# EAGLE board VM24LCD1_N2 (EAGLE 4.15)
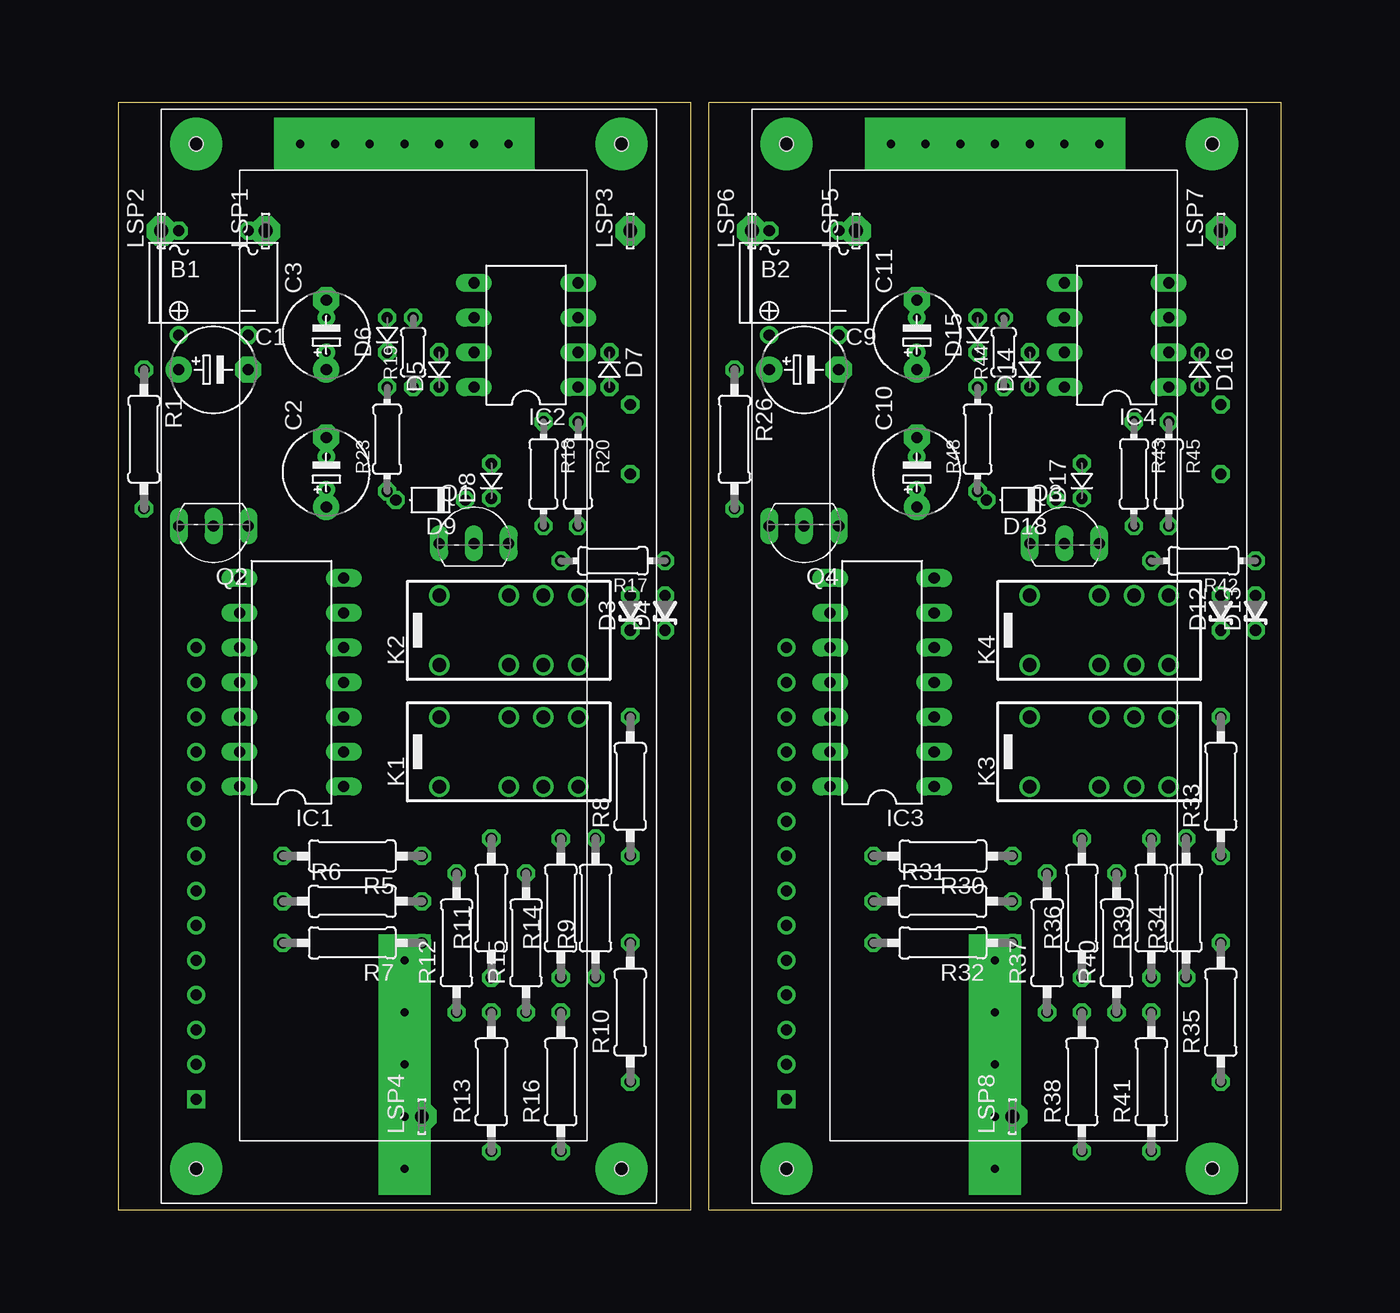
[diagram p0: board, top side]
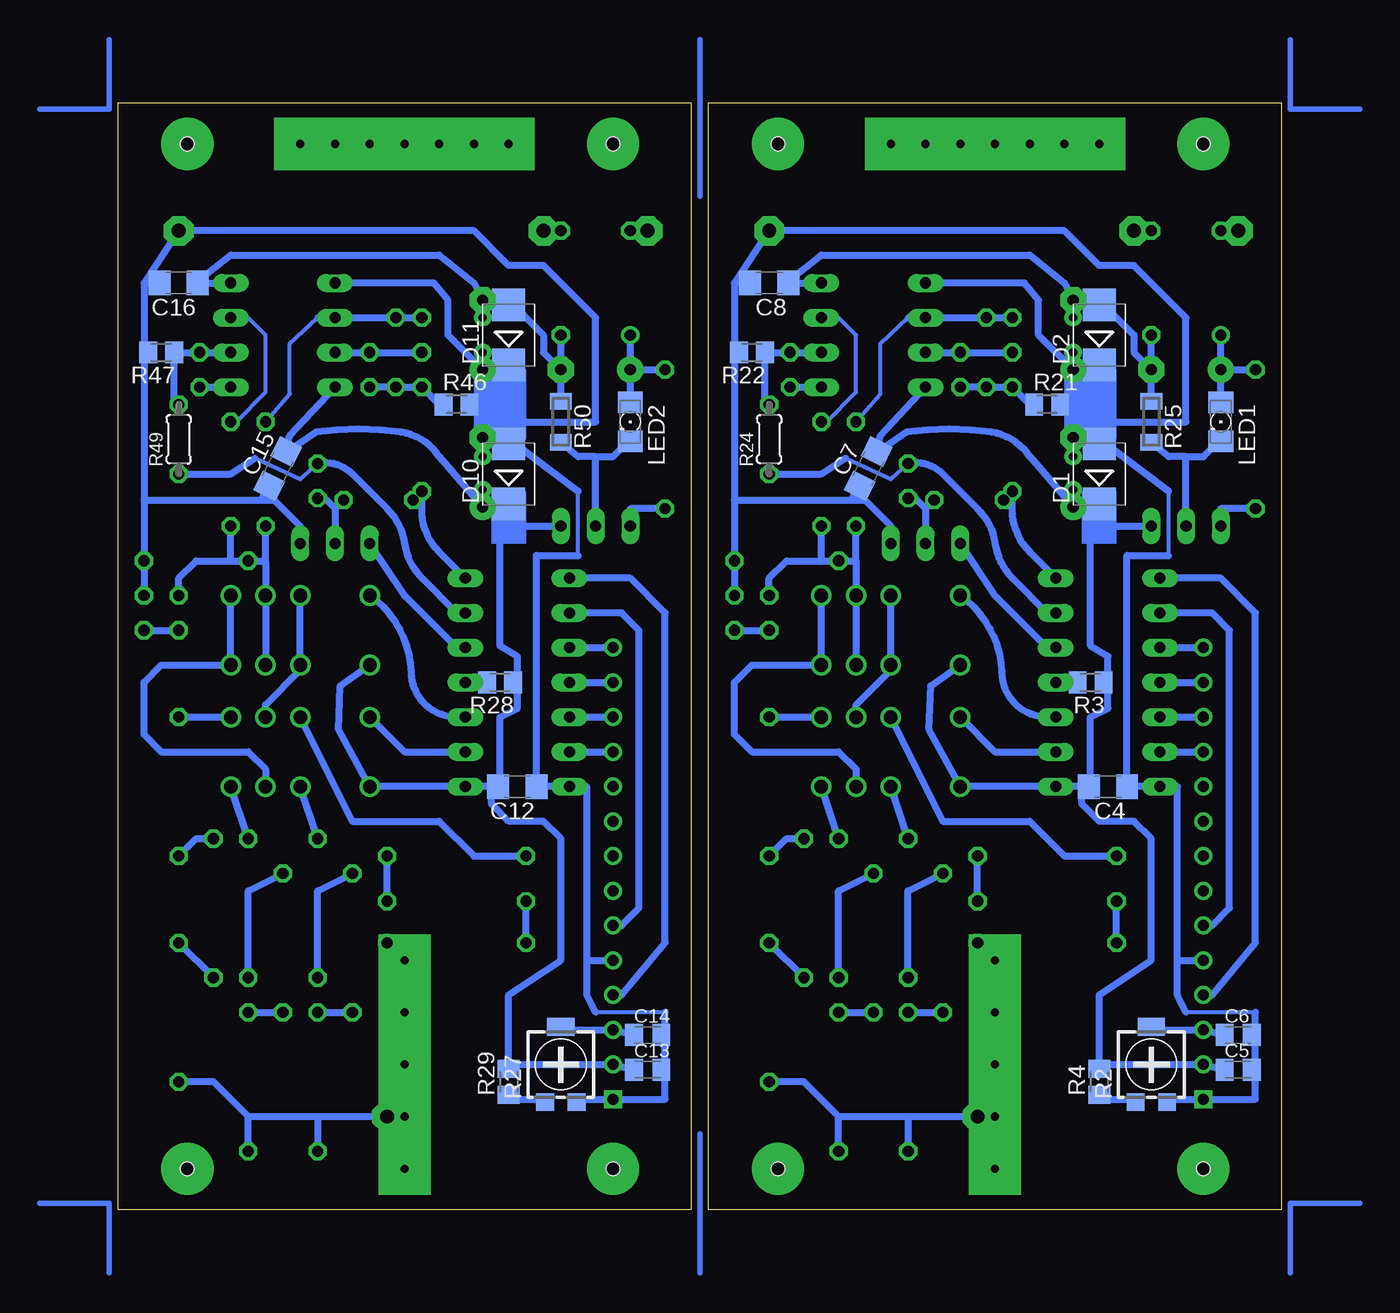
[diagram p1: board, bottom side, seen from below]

Size 85.08 x 80.95 mm. Coordinates in mm from the lower left corner, seen from the top.
Outline: 41.9,0 41.9,80.95 0,80.95 0,0 41.9,0
Outline: 85.08,0 85.08,80.95 43.18,80.95 43.18,0 85.08,0
Copper layers (1*16): Top 0.035mm / dielectric 1.5mm / Bottom 0.035mm
Design rules "default": minimum track width 10mil, minimum drill 24mil, track to track 8mil, track to pad 8mil, pad to pad 8mil, via to via 8mil, smd to smd 8mil, copper to edge 40mil, drill to drill 8mil, minimum pad ring 10mil, minimum via ring 8mil, stop-mask expansion 4mil, vias tented up to drill 0mil, thermal gap 10mil

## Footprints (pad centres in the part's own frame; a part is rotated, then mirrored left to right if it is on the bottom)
B-DIL = drill 0.813 round: + -2.54,-3.81 | drill 0.813 octagon: - 2.54,-3.81; AC1 2.54,3.81; AC2 -2.54,3.81
E5-6 = drill 0.813 pad 1.905 round: + -2.54,0 | drill 0.813 pad 1.905 octagon: - 2.54,0
C1206 = smd 1.6 x 1.8: 1 -1.4,0; 2 1.4,0
C0805K = smd 1.3 x 1.6: 1 -1,0; 2 1,0
SMB = smd 2.4 x 2.4: A 2.2,0; C -2.2,0
ZDIO-2.5 = drill 0.813 octagon: A 1.27,0; C -1.27,0
D-2.5 = drill 0.813 octagon: A 1.27,0; C -1.27,0
D-5 = drill 0.813 octagon: A 2.54,0; C -2.54,0
DIL14 = drill 0.813 long: 1 -7.62,-3.81; 2 -5.08,-3.81; 3 -2.54,-3.81; 4 0,-3.81; 5 2.54,-3.81; 6 5.08,-3.81; 7 7.62,-3.81; 8 7.62,3.81; 9 5.08,3.81; 10 2.54,3.81; 11 0,3.81; 12 -2.54,3.81; 13 -5.08,3.81; 14 -7.62,3.81
DIL08 = drill 0.813 long: 1 -3.81,-3.81; 2 -1.27,-3.81; 3 1.27,-3.81; 4 3.81,-3.81; 5 3.81,3.81; 6 1.27,3.81; 7 -1.27,3.81; 8 -3.81,3.81
TX2 = drill 1 round: 1 -5.08,-2.54; 3 0,-2.54; 4 2.54,-2.54; 5 5.08,-2.54; 8 5.08,2.54; 9 2.54,2.54; 10 0,2.54; 12 -5.08,2.54
1206 = smd 1.6 x 1.803: A -1.422,0; C 1.422,0
LSP10 = drill 1.016 pad 2.159 octagon: MP 0,0
TO92-EBC = drill 0.813 long: B 0,-1.27; C -2.54,-1.27; E 2.54,-1.27
0207/10 = drill 0.813 octagon: 1 -5.08,0; 2 5.08,0
RTRIM4G/J = smd 1.3 x 1.3: 1 -1.15,-2.75; 3 1.15,-2.75 | smd 2 x 1.3: 2 0,2.75
M0805 = smd 1.3 x 1.6: 1 -0.95,0; 2 0.95,0
0204/7 = drill 0.813 octagon: 1 -3.81,0; 2 3.81,0
0204/5 = drill 0.813 octagon: 1 -2.54,0; 2 2.54,0
MINI_MELF-0204W = smd 1.2 x 1.6: 1 -1.5,0; 2 1.5,0
LCD10X1P = drill 0.8 square: P$1 7.62,33.02 | drill 0.8 round: P$2 10.16,33.02; P$3 12.7,33.02; P$4 15.24,33.02; P$5 17.78,33.02; P$6 20.32,33.02; P$7 22.86,33.02; P$8 25.4,33.02; P$9 27.94,33.02; P$10 30.48,33.02; P$11 33.02,33.02; P$12 35.56,33.02; P$13 38.1,33.02; P$14 40.64,33.02 | hole 1: 2.54,1.905; 2.54,33.02; 77.47,33.02; 77.47,1.905

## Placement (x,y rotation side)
B1  [B-DIL]  6.98,67.78 0 top
B2  [B-DIL]  50.16,67.78 0 top
C1  220/25  [E5-6]  6.98,61.43 0 top
C2  47/6,3  [E5-6]  15.24,53.94 90 top
C3  47/6,3  [E5-6]  15.24,63.97 90 top
C4  100n  [C1206]  12.7,30.95 180 bottom
C5  100n  [C0805K]  3.17,10.25 0 bottom
C6  100n  [C0805K]  3.17,12.79 0 bottom
C7  100n  [C1206]  30.22,54.19 63.5 bottom
C8  100n  [C1206]  37.46,67.78 180 bottom
C9  220/25  [E5-6]  50.16,61.43 0 top
C10  47/6,3  [E5-6]  58.41,53.94 90 top
C11  47/6,3  [E5-6]  58.41,63.97 90 top
C12  100n  [C1206]  55.88,30.95 180 bottom
C13  100n  [C0805K]  46.35,10.25 0 bottom
C14  100n  [C0805K]  46.35,12.79 0 bottom
C15  100n  [C1206]  73.4,54.19 63.5 bottom
C16  100n  [C1206]  80.64,67.78 180 bottom
D1  5V1  [SMB]  13.33,53.81 90 bottom
D2  5V1  [SMB]  13.33,63.97 90 bottom
D3  3V3  [ZDIO-2.5]  37.46,43.65 90 top
D4  3V3  [ZDIO-2.5]  40,43.65 90 top
D5  1N4148  [D-2.5]  23.49,61.43 90 top
D6  1N4148  [D-2.5]  19.68,63.97 90 top
D7  1N4148  [D-2.5]  35.94,61.43 270 top
D8  1N4148  [D-2.5]  27.3,53.3 90 top
D9  1N4148  [D-5]  22.86,51.91 180 top
D10  5V1  [SMB]  56.51,53.81 90 bottom
D11  5V1  [SMB]  56.51,63.97 90 bottom
D12  3V3  [ZDIO-2.5]  80.64,43.65 90 top
D13  3V3  [ZDIO-2.5]  83.18,43.65 90 top
D14  1N4148  [D-2.5]  66.67,61.43 90 top
D15  1N4148  [D-2.5]  62.86,63.97 90 top
D16  1N4148  [D-2.5]  79.12,61.43 270 top
D17  1N4148  [D-2.5]  70.48,53.3 90 top
D18  1N4148  [D-5]  66.03,51.91 180 top
IC1  TINY24/44/84-PU  [DIL14]  12.7,38.57 90 top
IC2  TL072P  [DIL08]  29.84,63.97 90 top
IC3  TINY24/44/84-PU  [DIL14]  55.88,38.57 90 top
IC4  TL072P  [DIL08]  73.02,63.97 90 top
K1  TX2-4.5V  [TX2]  28.57,33.49 0 top
K2  TX2-4.5V  [TX2]  28.57,42.38 0 top
K3  TX2-4.5V  [TX2]  71.75,33.49 0 top
K4  TX2-4.5V  [TX2]  71.75,42.38 0 top
LED1  [1206]  4.44,57.62 270 bottom
LED2  [1206]  47.62,57.62 270 bottom
LSP1  LSP10  [LSP10]  10.79,71.59 90 top
LSP2  LSP10  [LSP10]  3.17,71.59 90 top
LSP3  LSP10  [LSP10]  37.46,71.59 90 top
LSP4  LSP10  [LSP10]  22.22,6.82 90 top
LSP5  LSP10  [LSP10]  53.97,71.59 90 top
LSP6  LSP10  [LSP10]  46.35,71.59 90 top
LSP7  LSP10  [LSP10]  80.64,71.59 90 top
LSP8  LSP10  [LSP10]  65.4,6.82 90 top
Q1  BC338  [TO92-EBC]  26.03,50 0 top
Q2  BC328  [TO92-EBC]  6.98,48.73 180 top
Q3  BC338  [TO92-EBC]  69.21,50 0 top
Q4  BC328  [TO92-EBC]  50.16,48.73 180 top
R1  39  [0207/10]  1.9,56.35 270 top
R2  20k  [RTRIM4G/J]  9.52,10.63 0 bottom
R3  10k  [M0805]  13.97,38.57 180 bottom
R4  22k  [M0805]  13.33,9.36 90 bottom
R5  [0207/10]  17.14,25.87 180 top
R6  [0207/10]  17.14,22.57 0 top
R7  [0207/10]  17.14,19.52 180 top
R8  [0207/10]  37.46,30.95 90 top
R9  [0207/10]  34.92,22.06 90 top
R10  [0207/10]  37.46,14.44 90 top
R11  [0207/10]  27.3,22.06 90 top
R12  [0207/10]  24.76,19.52 90 top
R13  [0207/10]  27.3,9.36 90 top
R14  [0207/10]  32.38,22.06 90 top
R15  [0207/10]  29.84,19.52 90 top
R16  [0207/10]  32.38,9.36 90 top
R17  22k  [0204/7]  36.19,47.46 180 top
R18  22k  [0204/7]  31.11,53.81 270 top
R19  22k  [0204/5]  21.58,62.7 90 top
R20  22k  [0204/7]  33.65,53.81 270 top
R21  10k  [M0805]  17.14,58.89 0 bottom
R22  10k  [M0805]  38.73,62.7 180 bottom
R23  10k  [0204/7]  19.68,56.35 90 top
R24  10k  [0204/5]  37.46,56.35 90 bottom
R25  2k  [MINI_MELF-0204W]  9.52,57.62 270 bottom
R26  39  [0207/10]  45.08,56.35 270 top
R27  20k  [RTRIM4G/J]  52.7,10.63 0 bottom
R28  10k  [M0805]  57.15,38.57 180 bottom
R29  22k  [M0805]  56.51,9.36 90 bottom
R30  [0207/10]  60.32,25.87 180 top
R31  [0207/10]  60.32,22.57 0 top
R32  [0207/10]  60.32,19.52 180 top
R33  [0207/10]  80.64,30.95 90 top
R34  [0207/10]  78.1,22.06 90 top
R35  [0207/10]  80.64,14.44 90 top
R36  [0207/10]  70.48,22.06 90 top
R37  [0207/10]  67.94,19.52 90 top
R38  [0207/10]  70.48,9.36 90 top
R39  [0207/10]  75.56,22.06 90 top
R40  [0207/10]  73.02,19.52 90 top
R41  [0207/10]  75.56,9.36 90 top
R42  22k  [0204/7]  79.37,47.46 180 top
R43  22k  [0204/7]  74.29,53.81 270 top
R44  22k  [0204/5]  64.77,62.7 90 top
R45  22k  [0204/7]  76.83,53.81 270 top
R46  10k  [M0805]  60.32,58.89 0 bottom
R47  10k  [M0805]  81.91,62.7 180 bottom
R48  10k  [0204/7]  62.86,56.35 90 top
R49  10k  [0204/5]  80.64,56.35 90 bottom
R50  2k  [MINI_MELF-0204W]  52.7,57.62 270 bottom
U$1  LCD10X1P  [LCD10X1P]  38.73,0.47 90 top
U$2  LCD10X1P  [LCD10X1P]  81.91,0.47 90 top

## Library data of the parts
B1 B2 = rectifier
C1-C16 R1-R50 = rcl
D1-D18 = diode
IC1 IC3 = avr-4
IC2 IC4 = linear
K1-K4 = relay
LED1 LED2 = led
LSP1-LSP8 = solpad
Q1 Q3 = transistor-npn
Q2 Q4 = transistor-pnp
U$1 U$2 = meine

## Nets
N$1: B1.+ C1.+ LED1.A R1.1
N$2: C2.+ C4.2 C5.1 C7.2 D1.C IC1.1 IC2.8 K1.1 K2.1 Q2.C R3.1 R4.2 U$1.P$2
N$3: C2.- C3.+ C4.1 C5.2 C6.2 C7.1 C8.2 D1.A D2.C D4.A IC1.14 IC2.5 LSP3.MP Q1.E R2.3 R17.1 R21.2 R22.2 U$1.P$1 U$1.P$5
N$4: B1.- C1.- C3.- C8.1 D2.A IC2.4 R25.1
N$5: IC1.10 U$1.P$14
N$6: IC1.11 U$1.P$13
N$7: IC1.12 U$1.P$12
N$8: IC1.13 U$1.P$11
N$9: IC1.9 U$1.P$6
N$10: IC1.8 U$1.P$4
N$11: R2.1 R4.1
N$12: C6.1 R2.2 U$1.P$3
N$13: IC1.2 K1.12
N$14: IC1.4 R3.2
N$15: IC1.3 K2.12
N$16: D3.A K2.4 K2.9 R17.2 R18.2 R20.2
N$17: K1.4 K2.5 K2.8
N$18: K1.9 K2.3 K2.10
N$19: K1.10 R5.2
N$20: R5.1 R6.2
N$21: R6.1 R7.2
N$22: K1.8 R8.2
N$23: R8.1 R9.2
N$24: R9.1 R10.2
N$25: K1.3 R11.2
N$26: R11.1 R12.2
N$27: R12.1 R13.2
N$28: K1.5 R14.2
N$29: R14.1 R15.2
N$30: R15.1 R16.2
N$31: LSP4.MP R7.1 R10.1 R13.1 R16.1
N$40: D3.C D4.C
N$41: D5.A D6.C IC2.7
N$42: D7.A IC2.1
N$43: D5.C R19.1 R21.1 R23.2
N$44: D6.A IC2.6 R18.1 R19.2
N$45: B1.AC1 LSP1.MP
N$46: IC2.3 R20.1
N$47: D7.C IC2.2 R22.1 R24.2
N$48: IC1.5 Q1.C
N$49: D8.C D9.C Q1.B
N$50: D8.A IC1.6 R24.1
N$51: D9.A IC1.7 R23.1
N$52: B1.AC2 LSP2.MP
N$61: Q2.E R1.2
N$62: LED1.C Q2.B R25.2
N$66: B2.+ C9.+ LED2.A R26.1
N$67: C10.+ C12.2 C13.1 C15.2 D10.C IC3.1 IC4.8 K3.1 K4.1 Q4.C R28.1 R29.2 U$2.P$2
N$68: C10.- C11.+ C12.1 C13.2 C14.2 C15.1 C16.2 D10.A D11.C D13.A IC3.14 IC4.5 LSP7.MP Q3.E R27.3 R42.1 R46.2 R47.2 U$2.P$1 U$2.P$5
N$69: B2.- C9.- C11.- C16.1 D11.A IC4.4 R50.1
N$70: IC3.10 U$2.P$14
N$71: IC3.11 U$2.P$13
N$72: IC3.12 U$2.P$12
N$73: IC3.13 U$2.P$11
N$74: IC3.9 U$2.P$6
N$75: IC3.8 U$2.P$4
N$76: C14.1 R27.2 U$2.P$3
N$77: IC3.4 R28.2
N$78: R27.1 R29.1
N$79: IC3.2 K3.12
N$80: IC3.3 K4.12
N$81: D12.A K4.4 K4.9 R42.2 R43.2 R45.2
N$82: K3.4 K4.5 K4.8
N$83: K3.9 K4.3 K4.10
N$84: K3.10 R30.2
N$85: R30.1 R31.2
N$86: R31.1 R32.2
N$87: K3.8 R33.2
N$88: R33.1 R34.2
N$89: R34.1 R35.2
N$90: K3.3 R36.2
N$91: R36.1 R37.2
N$92: R37.1 R38.2
N$93: K3.5 R39.2
N$94: R39.1 R40.2
N$95: R40.1 R41.2
N$96: LSP8.MP R32.1 R35.1 R38.1 R41.1
N$104: D12.C D13.C
N$105: D14.A D15.C IC4.7
N$106: D16.A IC4.1
N$107: D14.C R44.1 R46.1 R48.2
N$108: D15.A IC4.6 R43.1 R44.2
N$109: IC4.3 R45.1
N$110: D16.C IC4.2 R47.1 R49.2
N$111: IC3.5 Q3.C
N$112: D17.C D18.C Q3.B
N$113: D17.A IC3.6 R49.1
N$114: D18.A IC3.7 R48.1
N$115: B2.AC1 LSP5.MP
N$116: B2.AC2 LSP6.MP
N$126: Q4.E R26.2
N$127: LED2.C Q4.B R50.2

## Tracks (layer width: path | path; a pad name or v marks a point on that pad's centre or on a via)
N$1
  Bottom 0.508: C1.+ R1.1 | C1.+ B1.+ | LED1.A C1.+
N$2
  Bottom 0.508: C5.1 U$1.P$2 13.33,10.63 | R4.2 13.33,10.63 | 14.6,30.95 IC1.1 K1.1 25.78,35.14 25.65,38.32 K2.1 | 14.6,30.95 C4.2 13.97,30.95 13.97,36.03 12.7,36.66 12.7,38.57 | 13.33,10.63 13.33,15.71 9.52,18.25 9.52,27.14 10.79,28.41 13.33,28.41 14.6,29.68 14.6,30.95 | 12.7,38.57 12.7,40.48 13.97,41.24 13.97,51.4 | 12.7,38.57 R3.1 | 13.97,51.4 D1.C | 13.97,51.4 14.61,51.35 | 14.61,51.35 C2.+ 18.41,55.08 arc-48 21.2,56.86 arc-17 27.43,56.86 29.48,55.44 C7.2 29.59,55.46 29.33,56.6 IC2.8 | 14.61,51.35 14.61,51.28 13.33,50 Q2.C
N$3
  Bottom 0.305: 1.9,14.44 6.98,14.44 | 8.25,47.84 8.25,52.54
  Bottom 0.508: 8.25,30.95 7.62,30.95 7.62,18.25 | 8.25,30.95 IC1.14 | 7.62,18.25 U$1.P$5 | 7.62,18.25 7.62,15.71 6.98,14.44 | 1.9,10.63 1.9,8.09 U$1.P$1 8.37,8.09 R2.3 | 1.9,10.63 1.9,13.17 | 1.9,13.17 1.9,14.44 | 1.9,10.63 C5.2 | 1.9,13.17 C6.2 | 8.25,30.95 C4.1 11.29,47.84 8.25,47.84 | 8.25,52.54 13.33,56.35 D1.A 13.33,55.71 13.97,56.35 C2.- | D2.C 13.33,61.43 C3.+ | C2.- C3.+ | C3.+ 17.77,63.97 17.77,66.51 18.79,67.78 IC2.5 | C2.- 12.06,57.62 6.98,57.62 6.98,65.24 10.79,69.05 13.33,69.05 15.87,71.59 LSP3.MP 40,67.78 | D4.A R17.1 40,51.91 | 40,67.78 40,62.7 | 40,62.7 40,51.91 | 40,51.91 31.36,51.91 | 31.36,51.91 30.47,51.91 28.57,50 Q1.E | 31.36,51.91 31.36,52.03 C7.1 | 40,67.78 C8.2 | R21.2 15.87,58.89 15.24,58.25 C2.- | R22.2 40,62.7
N$4
  Bottom 0.508: C1.- B1.- | C1.- 10.79,62.7 10.79,63.97 12.99,66.17 D2.A 13.33,66.51 C3.- 15.87,67.78 18.41,69.81 33.65,69.81 36.06,67.91 C8.1 | C8.1 36.19,67.78 | C8.1 IC2.4 | R25.1 C1.-
N$5
  Bottom 0.508: IC1.10 U$1.P$14
N$6
  Bottom 0.508: IC1.11 U$1.P$13
N$7
  Bottom 0.508: IC1.12 U$1.P$12
N$8
  Bottom 0.508: IC1.13 U$1.P$11
N$9
  Bottom 0.508: IC1.9 5.08,43.65 3.8,42.38 3.8,22.06 5.08,20.79 U$1.P$6
N$10
  Bottom 0.508: IC1.8 4.44,46.19 1.9,43.65 1.9,19.52 5.08,15.71 U$1.P$4
N$11
  Bottom 0.508: R4.1 13.33,8.09 10.67,8.09 R2.1
N$12
  Bottom 0.508: C6.1 U$1.P$3 9.52,13.17 R2.2
N$13
  Bottom 0.508: IC1.2 20.95,33.49 K1.12
N$14
  Bottom 0.508: IC1.4 R3.2
N$15
  Bottom 0.508: IC1.3 17.14,36.03 arc90 20.44,39.33 arc-53 K2.12
N$16
  Bottom 0.508: K2.4 K2.9 31.11,47.46 | 33.65,47.46 36.19,47.46 37.46,46.19 D3.A | 33.65,47.46 R17.2 31.11,47.46 | 31.11,47.46 R18.2 | 33.65,47.46 R20.2
N$17
  Bottom 0.508: K1.4 31.11,32.22 32.38,33.49 38.73,33.49 40,34.76 40,38.57 38.73,39.84 K2.5 K2.8
N$18
  Bottom 0.508: K2.10 K2.3 28.57,39.46 31.11,36.92 K1.9
N$19
  Bottom 0.508: K1.10 24.76,28.41 18.41,28.41 15.87,25.87 R5.2
N$20
  Bottom 0.508: R6.2 R5.1
N$21
  Bottom 0.508: R7.2 R6.1
N$22
  Bottom 0.508: R8.2 K1.8
N$23
  Bottom 0.508: R9.2 36.19,27.14 R8.1
N$24
  Bottom 0.508: R10.2 R9.1
N$25
  Bottom 0.508: R11.2 K1.3
N$26
  Bottom 0.508: R11.1 27.3,23.33 R12.2
N$27
  Bottom 0.508: R13.2 R12.1
N$28
  Bottom 0.508: R14.2 K1.5
N$29
  Bottom 0.508: R14.1 32.38,23.33 R15.2
N$30
  Bottom 0.508: R16.2 R15.1
N$31
  Bottom 0.508: R10.1 34.92,9.36 32.38,6.82 | R16.1 32.38,6.82 | R7.1 LSP4.MP 27.3,6.82 | 32.38,6.82 27.3,6.82 | 27.3,6.82 R13.1
N$32  (via drill 0.6 pad 3.81)
  other vias: 20.95,3.01 20.95,6.82
N$33  (via drill 0.6 pad 3.81)
  other vias: 20.95,10.63
N$34  (via drill 0.6 pad 3.81)
  other vias: 20.95,14.44
N$35  (via drill 0.6 pad 3.81)
  other vias: 20.95,18.25
N$36  (via drill 0.6 pad 3.81)
  other vias: 5.71,3.01
N$37  (via drill 0.6 pad 3.81)
  other vias: 36.83,3.01
N$38  (via drill 0.6 pad 3.81)
  other vias: 36.83,77.94
N$39  (via drill 0.6 pad 3.81)
  other vias: 5.71,77.94
N$40
  Bottom 0.508: D4.C D3.C
N$41
  Bottom 0.508: D6.C D5.A IC2.7
N$42
  Bottom 0.508: D7.A IC2.1
N$43
  Bottom 0.508: D5.C 21.71,60.16 21.58,60.29 R19.1 R23.2 18.41,58.89 R21.1
N$44
  Bottom 0.305: R18.1 29.33,59.65 29.33,63.34 27.3,65.24
  Bottom 0.508: D6.A R19.2 IC2.6 27.3,65.24
N$45
  Bottom 0.508: LSP1.MP B1.AC1
N$46
  Bottom 0.305: R20.1 33.27,57.62 31.11,59.78 31.11,63.97 32.38,65.24 IC2.3
N$47
  Bottom 0.508: R24.2 arc90 37.78,59.21 R22.1 D7.C | D7.C 35.81,62.7 | 33.52,62.7 IC2.2 D7.C
N$48
  Bottom 0.508: IC1.5 17.14,41.11 20.95,44.92 Q1.C
N$49
  Bottom 0.508: 26.03,51.27 D9.C | 26.03,51.27 Q1.B | D8.C 26.79,52.03 26.03,51.27
N$50
  Bottom 0.305: D8.A 28.57,53.43 31.87,54.95
  Bottom 0.508: IC1.6 17.14,43.65 19.68,46.19 arc37 20.95,48.73 arc-37 22.22,51.27 24.76,53.81 arc-58 27.43,54.57 D8.A | 31.87,54.95 33.65,53.81 R24.1
N$51
  Bottom 0.508: 19.68,51.27 R23.1 | 19.68,51.27 D9.A | IC1.7 18.41,48.09 arc46 19.68,51.27
N$52
  Bottom 0.508: B1.AC2 LSP2.MP
N$53  (via drill 0.6 pad 1.27)
  other vias: 15.24,52.67
N$54  (via drill 0.6 pad 3.81)
  other vias: 28.57,77.94
N$55  (via drill 0.6 pad 3.81)
  other vias: 23.49,77.94
N$56  (via drill 0.6 pad 3.81)
  other vias: 18.41,77.94
N$57  (via drill 0.6 pad 3.81)
  other vias: 13.33,77.94
N$58  (via drill 0.6 pad 1.27)
  other vias: 15.24,55.08
N$59  (via drill 0.6 pad 1.27)
  other vias: 15.24,62.7
N$60  (via drill 0.6 pad 1.27)
  other vias: 15.24,65.24
N$61
  Bottom 0.508: R1.2 4.44,51.27 Q2.E
N$62
  Bottom 0.508: R25.2 8.25,55.08 6.98,55.08 | LED1.C 4.44,56.35 5.71,55.08 6.98,55.08 | Q2.B 6.98,55.08
N$63  (via drill 0.6 pad 3.81)
  other vias: 15.87,77.94
N$64  (via drill 0.6 pad 3.81)
  other vias: 20.95,77.94
N$65  (via drill 0.6 pad 3.81)
  other vias: 26.03,77.94
N$66
  Bottom 0.508: C9.+ R26.1 | C9.+ B2.+ | LED2.A C9.+
N$67
  Bottom 0.508: C13.1 U$2.P$2 56.51,10.63 | R29.2 56.51,10.63 | 57.78,30.95 IC3.1 K3.1 68.96,35.14 68.83,38.32 K4.1 | 57.78,30.95 C12.2 57.15,30.95 57.15,36.03 55.88,36.66 55.88,38.57 | 56.51,10.63 56.51,15.71 52.7,18.25 52.7,27.14 53.97,28.41 56.51,28.41 57.78,29.68 57.78,30.95 | 55.88,38.57 55.88,40.48 57.15,41.24 57.15,51.4 | 55.88,38.57 R28.1 | 57.15,51.4 D10.C | 57.15,51.4 57.79,51.35 | 57.79,51.35 C10.+ 61.59,55.08 arc-48 64.38,56.86 arc-17 70.61,56.86 72.66,55.44 C15.2 72.77,55.46 72.51,56.6 IC4.8 | 57.79,51.35 57.79,51.28 56.51,50 Q4.C
N$68
  Bottom 0.305: 45.08,14.44 50.16,14.44 | 51.43,47.84 51.43,52.54
  Bottom 0.508: 51.43,30.95 50.8,30.95 50.8,18.25 | 51.43,30.95 IC3.14 | 50.8,18.25 U$2.P$5 | 50.8,18.25 50.8,15.71 50.16,14.44 | 45.08,10.63 45.08,8.09 U$2.P$1 51.55,8.09 R27.3 | 45.08,10.63 45.08,13.17 | 45.08,13.17 45.08,14.44 | 45.08,10.63 C13.2 | 45.08,13.17 C14.2 | 51.43,30.95 C12.1 54.48,47.84 51.43,47.84 | 51.43,52.54 56.51,56.35 D10.A 56.51,55.71 57.15,56.35 C10.- | D11.C 56.51,61.43 C11.+ | C10.- C11.+ | C11.+ 60.96,63.97 60.96,66.51 61.97,67.78 IC4.5 | C10.- 55.24,57.62 50.16,57.62 50.16,65.24 53.97,69.05 56.51,69.05 59.05,71.59 LSP7.MP 83.18,67.78 | D13.A R42.1 83.18,51.91 | 83.18,67.78 83.18,62.7 | 83.18,62.7 83.18,51.91 | 83.18,51.91 74.54,51.91 | 74.54,51.91 73.66,51.91 71.75,50 Q3.E | 74.54,51.91 74.54,52.03 C15.1 | 83.18,67.78 C16.2 | R46.2 59.05,58.89 58.41,58.25 C10.- | R47.2 83.18,62.7
N$69
  Bottom 0.508: C9.- B2.- | C9.- 53.97,62.7 53.97,63.97 56.17,66.17 D11.A 56.51,66.51 C11.- 59.05,67.78 61.59,69.81 76.83,69.81 79.24,67.91 C16.1 | C16.1 79.37,67.78 | C16.1 IC4.4 | R50.1 C9.-
N$70
  Bottom 0.508: IC3.10 U$2.P$14
N$71
  Bottom 0.508: IC3.11 U$2.P$13
N$72
  Bottom 0.508: IC3.12 U$2.P$12
N$73
  Bottom 0.508: IC3.13 U$2.P$11
N$74
  Bottom 0.508: IC3.9 48.26,43.65 46.98,42.38 46.98,22.06 48.26,20.79 U$2.P$6
N$75
  Bottom 0.508: IC3.8 47.62,46.19 45.08,43.65 45.08,19.52 48.26,15.71 U$2.P$4
N$76
  Bottom 0.508: C14.1 U$2.P$3 52.7,13.17 R27.2
N$77
  Bottom 0.508: IC3.4 R28.2
N$78
  Bottom 0.508: R29.1 56.51,8.09 53.85,8.09 R27.1
N$79
  Bottom 0.508: IC3.2 64.13,33.49 K3.12
N$80
  Bottom 0.508: IC3.3 60.32,36.03 arc90 63.62,39.33 arc-53 K4.12
N$81
  Bottom 0.508: K4.4 K4.9 74.29,47.46 | 76.83,47.46 79.37,47.46 80.64,46.19 D12.A | 76.83,47.46 R42.2 74.29,47.46 | 74.29,47.46 R43.2 | 76.83,47.46 R45.2
N$82
  Bottom 0.508: K3.4 74.29,32.22 75.56,33.49 81.91,33.49 83.18,34.76 83.18,38.57 81.91,39.84 K4.5 K4.8
N$83
  Bottom 0.508: K4.10 K4.3 71.75,39.46 74.29,36.92 K3.9
N$84
  Bottom 0.508: K3.10 67.94,28.41 61.59,28.41 59.05,25.87 R30.2
N$85
  Bottom 0.508: R31.2 R30.1
N$86
  Bottom 0.508: R32.2 R31.1
N$87
  Bottom 0.508: R33.2 K3.8
N$88
  Bottom 0.508: R34.2 79.37,27.14 R33.1
N$89
  Bottom 0.508: R35.2 R34.1
N$90
  Bottom 0.508: R36.2 K3.3
N$91
  Bottom 0.508: R36.1 70.48,23.33 R37.2
N$92
  Bottom 0.508: R38.2 R37.1
N$93
  Bottom 0.508: R39.2 K3.5
N$94
  Bottom 0.508: R39.1 75.56,23.33 R40.2
N$95
  Bottom 0.508: R41.2 R40.1
N$96
  Bottom 0.508: R35.1 78.1,9.36 75.56,6.82 | R41.1 75.56,6.82 | R32.1 LSP8.MP 70.48,6.82 | 75.56,6.82 70.48,6.82 | 70.48,6.82 R38.1
N$97  (via drill 0.6 pad 3.81)
  other vias: 64.13,3.01 64.13,6.82
N$98  (via drill 0.6 pad 3.81)
  other vias: 64.13,10.63
N$99  (via drill 0.6 pad 3.81)
  other vias: 64.13,14.44
N$100  (via drill 0.6 pad 3.81)
  other vias: 64.13,18.25
N$101  (via drill 0.6 pad 3.81)
  other vias: 48.89,3.01
N$102  (via drill 0.6 pad 3.81)
  other vias: 80,3.01
N$103  (via drill 0.6 pad 3.81)
  other vias: 80,77.94
N$104
  Bottom 0.508: D13.C D12.C
N$105
  Bottom 0.508: D15.C D14.A IC4.7
N$106
  Bottom 0.508: D16.A IC4.1
N$107
  Bottom 0.508: D14.C 64.89,60.16 64.77,60.29 R44.1 R48.2 61.59,58.89 R46.1
N$108
  Bottom 0.305: R43.1 72.51,59.65 72.51,63.34 70.48,65.24
  Bottom 0.508: D15.A R44.2 IC4.6 70.48,65.24
N$109
  Bottom 0.305: R45.1 76.45,57.62 74.29,59.78 74.29,63.97 75.56,65.24 IC4.3
N$110
  Bottom 0.508: R49.2 arc90 80.96,59.21 R47.1 D16.C | D16.C 78.99,62.7 | 76.7,62.7 IC4.2 D16.C
N$111
  Bottom 0.508: IC3.5 60.32,41.11 64.13,44.92 Q3.C
N$112
  Bottom 0.508: 69.21,51.27 D18.C | 69.21,51.27 Q3.B | D17.C 69.97,52.03 69.21,51.27
N$113
  Bottom 0.305: D17.A 71.75,53.43 75.05,54.95
  Bottom 0.508: IC3.6 60.32,43.65 62.86,46.19 arc37 64.13,48.73 arc-37 65.4,51.27 67.94,53.81 arc-58 70.61,54.57 D17.A | 75.05,54.95 76.83,53.81 R49.1
N$114
  Bottom 0.508: 62.86,51.27 R48.1 | 62.86,51.27 D18.A | IC3.7 61.59,48.09 arc46 62.86,51.27
N$115
  Bottom 0.508: LSP5.MP B2.AC1
N$116
  Bottom 0.508: B2.AC2 LSP6.MP
N$117  (via drill 0.6 pad 3.81)
  other vias: 71.75,77.94
N$118  (via drill 0.6 pad 3.81)
  other vias: 66.67,77.94
N$119  (via drill 0.6 pad 3.81)
  other vias: 61.59,77.94
N$120  (via drill 0.6 pad 3.81)
  other vias: 48.89,77.94
N$121  (via drill 0.6 pad 3.81)
  other vias: 56.51,77.94
N$122  (via drill 0.6 pad 1.27)
  other vias: 58.41,52.67
N$123  (via drill 0.6 pad 1.27)
  other vias: 58.41,55.08
N$124  (via drill 0.6 pad 1.27)
  other vias: 58.41,62.7
N$125  (via drill 0.6 pad 1.27)
  other vias: 58.41,65.24
N$126
  Bottom 0.508: R26.2 47.62,51.27 Q4.E
N$127
  Bottom 0.508: R50.2 51.43,55.08 50.16,55.08 | LED2.C 47.62,56.35 48.89,55.08 50.16,55.08 | Q4.B 50.16,55.08
N$128  (via drill 0.6 pad 3.81)
  other vias: 59.05,77.94
N$129  (via drill 0.6 pad 3.81)
  other vias: 64.13,77.94
N$130  (via drill 0.6 pad 3.81)
  other vias: 69.21,77.94
S$1
  Bottom 0.406: -5.72,0.47 -0.64,0.47 -0.64,-4.61
S$2
  Bottom 0.406: -5.72,80.48 -0.64,80.48 -0.64,85.56
S$3
  Bottom 0.406: 90.8,80.48 85.72,80.48 85.72,85.56
S$4
  Bottom 0.406: 90.8,0.47 85.72,0.47 85.72,-4.61
S$5
  Bottom 0.406: 42.54,-4.61 42.54,5.55
S$6
  Bottom 0.406: 42.54,85.56 42.54,74.13
(copper drawn outside any net)
  shapes: Bottom area x4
